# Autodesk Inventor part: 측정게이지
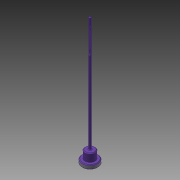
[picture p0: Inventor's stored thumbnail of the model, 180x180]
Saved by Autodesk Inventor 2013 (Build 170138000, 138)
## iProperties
Created: 2017-05
Part Number: 측정게이지
Material: 스테인리스강
Document SubType Name: Modeling
Designer: mduedu
Density: 8.08 g/cm^3
Mass: 39.5088 g
Surface Area: 29.9761 cm^2
Volume: 4.8897 cm^3
Author: mduedu
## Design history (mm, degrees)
sketch "스케치1"
  geometry: C1 r 11 at (0, 0); 1 further point
  constraints: 1 centre point, 1 coincident
  dimensions: "d0" = 22 diameter of C1
extrude "돌출1" new body sketch "스케치1" distance "d2" = 6; taper "d3" = 0 deg
sketch "스케치2"
  geometry: C1 r 7 at (0, 0); 1 further point
  constraints: 1 centre point, 1 coincident
  dimensions: "d4" = 14 diameter of C1
extrude "돌출2" join sketch "스케치2" distance "d5" = 11; taper "d6" = 0 deg
sketch "스케치3"
  geometry: C1 r 1.5 at (0, 0); 1 further point
  constraints: 1 centre point, 1 coincident
  dimensions: "d7" = 3 diameter of C1
extrude "돌출3" join sketch "스케치3" distance "d8" = 160; taper "d9" = 0 deg
fillet "모깎기1" dims "d10" = 1
chamfer "모따기1" distance "d11" = 1; stored, may be unused: second distance "d12" = 2, angle "d13" = 45 deg
sketch "스케치4"
  geometry: L1 (16, 7)-(17, 6) reference; L2 (6, 7)-(16, 7) reference; L3 (16, -7)-(6, -7) reference; L4 (17, -6)-(16, -7) reference; L5 (17, 6)-(17, 2.5) reference; L6 (18, 1.5)-(176, 1.5) reference; L7 (176, 1.5)-(177, 0.5) reference; L8 (177, 0.5)-(177, -0.5) reference; L9 (177, -0.5)-(176, -1.5) reference; L10 (176, -1.5)-(18, -1.5) reference; L11 (17, -2.5)-(17, -6) reference; L12 (177, 0)-(0, 0); L13 (167, 0)-(131, 0); L14 (131, 0)-(131, 1.5); L15 (131, 1.5)-(167, 1.5); L16 (167, 1.5)-(167, 0); L17 (0, 11)-(6, 11) reference; L18 (6, 11)-(6, 7) reference; L19 (6, -7)-(6, -11) reference; L20 (6, -11)-(0, -11) reference; L21 (0, -11)-(0, 11) reference; A1 r 1 centre (18, 2.5) between (17, 2.5) and (18, 1.5) reference; A2 r 1 centre (18, -2.5) between (18, -1.5) and (17, -2.5) reference
  constraints: 10 end point, 2 parallel, 2 point on line, 1 horizontal, 1 midpoint, 1 perpendicular
  dimensions: "d14" = 10 distance from line of L16 L7.end; "d15" = 36 distance between parallel lines of L14 L16
extrude "돌출4" cut sketch "스케치4" stored distance "d16" = 160; taper "d17" = 0 deg
sketch "스케치5"
  geometry: L1 (0, 0)-(3, 0) reference; L2 (3, 36)-(0, 36) reference; L3 (1.5, 0)-(1.5, 36); 3 further points
  constraints: 2 end point, 2 midpoint, 2 point on line, 2 other
  dimensions: "d18" = 5 distance from line of point (1.5, 5) L1; "d19" = 5 distance from line of point (1.5, 31) L2
feature "엠보싱1" sketch "스케치5" dims "d20" = 0.3, "d21" = 0
chamfer "모따기2" distance "d32" = 1; stored, may be unused: second distance "d33" = 2, angle "d34" = 45 deg
node "솔리드1"
node "절단 모서리 투영1"
